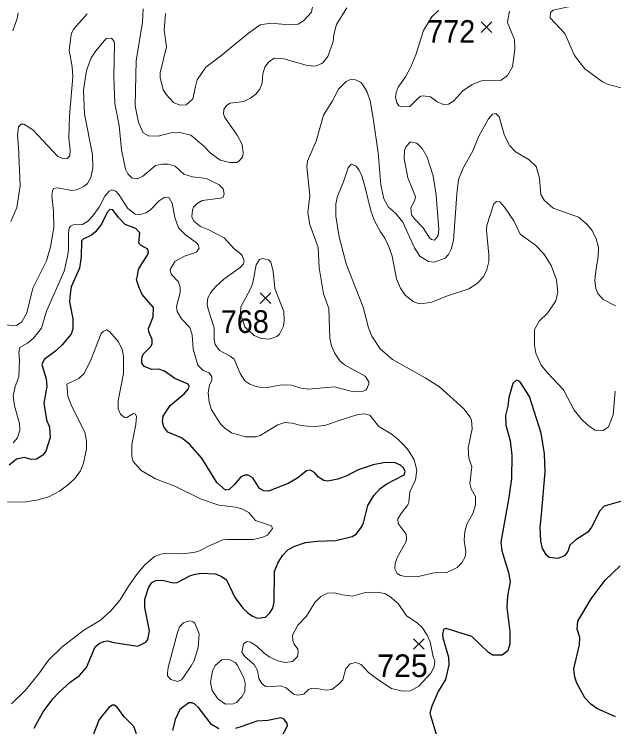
# Model space of a CAD drawing. Extents: x 294.2 to 320.3, y 7482.7 to 7510.7.
# Drawn here: x 306.916 to 309.032, y 7498.807 to 7501.322 of the extents above; entities that cross this region are included whole.
import ezdxf
from ezdxf.enums import TextEntityAlignment as Align

# ---------------------------------------------------------------- set-up
doc = ezdxf.new("R2010")
doc.units = 0
doc.header["$LTSCALE"] = 0.032
for name, color, linetype, lineweight in [('1', 7, 'Continuous', 25), ('2', 7, 'Continuous', 13), ('21', 7, 'Continuous', 25)]:
    doc.layers.add(name, color=color, linetype=linetype, lineweight=lineweight)
doc.layers.add('61', color=7, linetype='Continuous')

msp = doc.modelspace()

# ---------------------------------------------------------------- linework, layer by layer
at = {"layer": '1'}
for points in [[(307.5349, 7499.8047), (307.5058, 7499.8267), (307.4579, 7499.8471), (307.4445, 7499.8652), (307.4394, 7499.8833), (307.4418, 7499.9029), (307.452, 7499.9202), (307.4661, 7499.9407), (307.5157, 7499.9816), (307.5298, 7499.9981), (307.5338, 7500.0075), (307.5298, 7500.0162), (307.4833, 7500.0366), (307.4463, 7500.0625), (307.4266, 7500.0696), (307.4015, 7500.068), (307.3748, 7500.079), (307.3669, 7500.0908), (307.3669, 7500.1074), (307.3708, 7500.1223), (307.3968, 7500.1475), (307.4031, 7500.1585), (307.4033, 7500.1734), (307.3912, 7500.2007), (307.3904, 7500.2132), (307.4062, 7500.2541), (307.407, 7500.2864), (307.3671, 7500.3328), (307.3561, 7500.3595), (307.3479, 7500.3844), (307.3508, 7500.3988), (307.3541, 7500.421), (307.3665, 7500.4404), (307.3858, 7500.4719), (307.3897, 7500.4821), (307.3881, 7500.4931), (307.3639, 7500.5062), (307.3559, 7500.5144), (307.359, 7500.5505), (307.3457, 7500.5655), (307.3071, 7500.5796), (307.2838, 7500.604), (307.2642, 7500.6315), (307.2531, 7500.6323), (307.2453, 7500.6244), (307.2243, 7500.5812), (307.2033, 7500.5537), (307.1892, 7500.5422), (307.1592, 7500.5282), (307.1535, 7500.5224), (307.1522, 7500.4662), (307.1458, 7500.4254), (307.1164, 7500.3602), (307.1133, 7500.3347), (307.1115, 7500.3064), (307.1225, 7500.2474), (307.1225, 7500.2113), (307.117, 7500.1932), (307.0852, 7500.1555), (307.0624, 7500.1334), (307.0215, 7500.1028), (307.0136, 7500.0855), (307.029, 7500.0351), (307.0313, 7500.0076), (307.0203, 7499.9494), (307.0301, 7499.8905), (307.0403, 7499.8645), (307.043, 7499.8284), (307.0277, 7499.7793), (307.0168, 7499.7658), (306.9951, 7499.7518), (306.9753, 7499.7505), (306.9524, 7499.7569), (306.9243, 7499.7518), (306.8987, 7499.7301)], [(309.0967, 7499.6135), (308.998, 7499.5852), (308.9823, 7499.5695), (308.9532, 7499.5113), (308.9399, 7499.494), (308.8978, 7499.4673), (308.8774, 7499.4484), (308.8695, 7499.4256), (308.8585, 7499.4107), (308.8349, 7499.4013), (308.8042, 7499.4044), (308.794, 7499.4123), (308.7799, 7499.4367), (308.7746, 7499.4626), (308.7726, 7499.5098), (308.7771, 7499.5558), (308.7899, 7499.7072), (308.788, 7499.7705), (308.7761, 7499.8429), (308.7345, 7499.9726), (308.6999, 7500.0261), (308.6889, 7500.0308), (308.6755, 7500.019), (308.6618, 7499.9697), (308.6581, 7499.939), (308.6494, 7499.906), (308.651, 7499.8714), (308.6666, 7499.8156), (308.6724, 7499.7639), (308.6705, 7499.6835), (308.6613, 7499.6159), (308.6328, 7499.4587), (308.6367, 7499.4281), (308.6609, 7499.3515), (308.666, 7499.3183), (308.6571, 7499.2685), (308.6545, 7499.2276), (308.6647, 7499.1428), (308.6655, 7499.0995), (308.6576, 7499.0744), (308.6379, 7499.0594), (308.6041, 7499.0594), (308.59, 7499.0689), (308.5307, 7499.125), (308.4403, 7499.1541), (308.4309, 7499.1501), (308.427, 7499.1336), (308.4285, 7499.1203), (308.4485, 7499.0528), (308.4493, 7499.0252), (308.4379, 7498.9733), (308.412, 7498.9309), (308.39, 7498.8798), (308.3833, 7498.8546), (308.4077, 7498.7721)], [(307.7152, 7499.6896), (307.6932, 7499.6621), (307.6743, 7499.6448), (307.6617, 7499.6417), (307.6313, 7499.6692), (307.5781, 7499.755), (307.5349, 7499.8047)], [(306.9862, 7498.8018), (307.0176, 7498.8592), (307.0526, 7498.9056), (307.073, 7498.9276), (307.1131, 7498.9646), (307.1448, 7498.9866), (307.1705, 7499.0162), (307.2019, 7499.0886), (307.2161, 7499.1004), (307.2318, 7499.1082), (307.2452, 7499.1106), (307.2676, 7499.1043), (307.3525, 7499.0918), (307.38, 7499.1051), (307.3871, 7499.1153), (307.3934, 7499.146), (307.3771, 7499.2278), (307.3771, 7499.2577), (307.3893, 7499.297), (307.4011, 7499.3159), (307.4153, 7499.3237), (307.4389, 7499.3245), (307.4774, 7499.3151), (307.4916, 7499.3159), (307.5385, 7499.3404), (307.5558, 7499.3459), (307.5766, 7499.349), (307.6246, 7499.3467), (307.6458, 7499.338), (307.6647, 7499.3255), (307.6949, 7499.2635), (307.7244, 7499.2242), (307.7409, 7499.2093), (307.7574, 7499.1975), (307.7747, 7499.1904), (307.8022, 7499.1936), (307.818, 7499.2085), (307.8282, 7499.2258), (307.8337, 7499.2463), (307.8349, 7499.3547), (307.8459, 7499.3846), (307.8624, 7499.4113), (307.8821, 7499.431), (307.9029, 7499.4428), (307.9445, 7499.4577), (307.9846, 7499.4624), (308.0511, 7499.4648), (308.1092, 7499.4789), (308.1226, 7499.4868), (308.1415, 7499.512), (308.1488, 7499.5269), (308.1641, 7499.5881), (308.185, 7499.6234), (308.2062, 7499.6462), (308.229, 7499.6635), (308.2919, 7499.6958), (308.2958, 7499.7076), (308.2903, 7499.7209), (308.2793, 7499.7304), (308.2577, 7499.7398), (308.2191, 7499.7383), (308.1822, 7499.732), (308.1299, 7499.7139), (308.0898, 7499.6927), (308.0575, 7499.6809), (308.0229, 7499.6738), (308.0084, 7499.6762), (307.9903, 7499.688), (307.9762, 7499.7045), (307.9604, 7499.7132), (307.9479, 7499.7108), (307.9172, 7499.6857), (307.883, 7499.666), (307.8138, 7499.6385), (307.7973, 7499.6401), (307.7816, 7499.648), (307.7576, 7499.6857), (307.7419, 7499.6951), (307.7293, 7499.6951), (307.7152, 7499.6896)], [(309.0381, 7498.8419), (308.9725, 7498.8711), (308.9504, 7498.8868), (308.93, 7498.9096), (308.9013, 7498.9607), (308.8942, 7498.9819), (308.8911, 7499.011), (308.9111, 7499.0959), (308.9119, 7499.1219), (308.9032, 7499.151), (308.9056, 7499.1793), (308.9522, 7499.2579), (309.001, 7499.324), (309.0547, 7499.3751)], [(307.6377, 7498.7996), (307.6125, 7498.8146), (307.5666, 7498.8745), (307.5538, 7498.8866), (307.5436, 7498.8918), (307.5321, 7498.8918), (307.5002, 7498.8675), (307.4834, 7498.8325), (307.4747, 7498.7932)], [(307.3378, 7498.8081), (307.304, 7498.8419), (307.2788, 7498.8757), (307.2702, 7498.8836), (307.2631, 7498.8828), (307.2498, 7498.875), (307.2154, 7498.8325)], [(307.2154, 7498.8325), (307.1714, 7498.7184)], [(307.8579, 7498.7682), (307.8799, 7498.8098), (307.8791, 7498.8185), (307.8681, 7498.8334), (307.8571, 7498.8381), (307.8111, 7498.8295), (307.7726, 7498.8264), (307.7195, 7498.8083), (307.6967, 7498.8012)], [(307.3472, 7498.7822), (307.3378, 7498.8081)]]:
    msp.add_lwpolyline(points, dxfattribs=at)
at = {"layer": '2'}
for points in [[(307.9675, 7501.74), (308.0026, 7501.7151), (308.0141, 7501.6985), (308.0314, 7501.6628), (308.0435, 7501.6181), (308.0454, 7501.5951), (308.0339, 7501.53), (308.0211, 7501.4968), (308.0001, 7501.461), (307.9815, 7501.4201), (307.9656, 7501.3288), (307.9369, 7501.2982), (307.9177, 7501.2873), (307.873, 7501.2854), (307.822, 7501.2899), (307.7837, 7501.2841), (307.7428, 7501.2548), (307.6445, 7501.1737), (307.5927, 7501.1347), (307.5621, 7501.0907), (307.5556, 7501.067)], [(309.0344, 7501.3626), (309.0108, 7501.3761), (308.954, 7501.392), (308.9368, 7501.3914), (308.9125, 7501.3844), (308.8831, 7501.355), (308.8722, 7501.3486), (308.8333, 7501.3397), (308.818, 7501.3358), (308.8084, 7501.3282), (308.8077, 7501.3096), (308.8588, 7501.2541), (308.8933, 7501.1762), (308.9297, 7501.1296), (308.9923, 7501.0837), (309.0095, 7501.0753), (309.0964, 7501.0517)], [(308.0901, 7501.3448), (308.0531, 7501.2861), (308.0435, 7501.2503), (308.0416, 7501.226), (308.0231, 7501.1724), (308.0039, 7501.1488), (307.9816, 7501.1398), (307.9727, 7501.1392), (307.9458, 7501.1424), (307.8679, 7501.1641), (307.8334, 7501.1667), (307.813, 7501.1532), (307.8002, 7501.1347), (307.7938, 7501.1111), (307.7913, 7501.0792), (307.783, 7501.0575), (307.769, 7501.0402), (307.7498, 7501.0262), (307.7262, 7501.014), (307.6777, 7501.0083), (307.6649, 7501), (307.6553, 7500.9853), (307.654, 7500.9707), (307.6592, 7500.9579), (307.7026, 7500.8953), (307.7204, 7500.8627), (307.7243, 7500.8315), (307.7217, 7500.8174), (307.7102, 7500.804), (307.7013, 7500.7989), (307.6777, 7500.7982), (307.6432, 7500.8072), (307.6074, 7500.8327), (307.5844, 7500.857), (307.5397, 7500.8953), (307.5002, 7500.9049), (307.4683, 7500.9036), (307.4236, 7500.8921), (307.3904, 7500.8927), (307.3705, 7500.9036), (307.354, 7500.94), (307.3431, 7500.9987), (307.3469, 7501.1571), (307.3686, 7501.2937), (307.3712, 7501.341)], [(308.4138, 7501.3346), (308.3896, 7501.3128), (308.3608, 7501.265), (308.3334, 7501.1788), (308.3155, 7501.1367), (308.2964, 7501.1009), (308.2714, 7501.0651), (308.2637, 7501.046), (308.2612, 7501.0281), (308.2663, 7501.0102), (308.2733, 7500.9981), (308.2823, 7500.9949), (308.3117, 7500.9962), (308.341, 7501.0255), (308.3513, 7501.0332), (308.3596, 7501.0345), (308.3851, 7501.03), (308.4087, 7501.0127), (308.4311, 7501.0032), (308.4489, 7501.0051), (308.4674, 7501.016), (308.4994, 7501.0517), (308.5319, 7501.0734), (308.5651, 7501.0868), (308.6347, 7501.0888), (308.6571, 7501.1054), (308.6749, 7501.1367), (308.6826, 7501.1992), (308.682, 7501.2331), (308.6571, 7501.2924), (308.6577, 7501.3027), (308.6641, 7501.3333)], [(307.1739, 7501.3231), (307.1267, 7501.2707), (307.1183, 7501.2554), (307.1152, 7501.2414), (307.1094, 7501.1954), (307.1209, 7501.1367), (307.1234, 7501.1009), (307.1107, 7500.963), (307.1088, 7500.8851), (307.1139, 7500.843), (307.112, 7500.8225), (307.103, 7500.8129), (307.0916, 7500.8117), (307.0698, 7500.8199), (306.9811, 7500.9145), (306.9498, 7500.9343), (306.9402, 7500.9336), (306.9306, 7500.924), (306.9281, 7500.894), (306.9313, 7500.8532), (306.9364, 7500.7165), (306.9255, 7500.6399), (306.9045, 7500.5901)], [(306.93, 7501.3269), (306.9262, 7501.3065), (306.9115, 7501.2637)], [(307.5556, 7501.067), (307.5468, 7501.0236), (307.5232, 7501.0025), (307.5002, 7501.0007), (307.4778, 7501.0102), (307.4529, 7501.037), (307.4421, 7501.0549), (307.4306, 7501.0984), (307.4306, 7501.115), (307.4536, 7501.2069), (307.4452, 7501.2656), (307.4497, 7501.3244)], [(307.9815, 7500.8736), (307.9509, 7500.8034), (307.9483, 7500.7829), (307.9592, 7500.6821), (307.9522, 7500.6208), (307.9598, 7500.5799), (307.9892, 7500.4982), (307.9924, 7500.4267), (308.0071, 7500.3347), (308.0262, 7500.2837), (308.0301, 7500.1789), (308.0352, 7500.1521), (308.046, 7500.1272), (308.0646, 7500.0985), (308.0818, 7500.0844), (308.1546, 7500.0448), (308.1674, 7500.0244), (308.1674, 7500.0168), (308.1603, 7500.0001), (308.1565, 7499.995), (308.1444, 7499.9899), (308.1131, 7499.9886), (308.0467, 7500.0065), (307.9548, 7499.9982), (307.9292, 7500.0021), (307.8935, 7500.0129), (307.859, 7500.0142), (307.8104, 7500.004), (307.7926, 7500.0034), (307.7658, 7500.0097), (307.7479, 7500.0161), (307.7294, 7500.0282), (307.7128, 7500.0538), (307.6917, 7500.1042), (307.6777, 7500.1151), (307.64, 7500.1349), (307.6253, 7500.1559), (307.6221, 7500.1738), (307.6221, 7500.2147), (307.6004, 7500.2811), (307.5972, 7500.299), (307.5991, 7500.3213), (307.6093, 7500.3398), (307.6259, 7500.3602), (307.6553, 7500.3864), (307.7134, 7500.4279), (307.7249, 7500.4407), (307.7274, 7500.4509), (307.7204, 7500.4701), (307.7115, 7500.4803), (307.6917, 7500.4944), (307.6572, 7500.5333), (307.6023, 7500.5614), (307.573, 7500.5722), (307.5499, 7500.592), (307.5429, 7500.6067), (307.5448, 7500.631), (307.5487, 7500.6406), (307.5615, 7500.6539), (307.5793, 7500.6641), (307.6444, 7500.6725), (307.6528, 7500.6763), (307.6572, 7500.6884), (307.6528, 7500.7056), (307.6387, 7500.7197), (307.594, 7500.7427), (307.5449, 7500.7478), (307.5148, 7500.7574), (307.4842, 7500.7861), (307.4593, 7500.7925), (307.4389, 7500.7931), (307.4146, 7500.788), (307.3686, 7500.7497), (307.3501, 7500.7414), (307.3322, 7500.7433), (307.3175, 7500.7587), (307.3086, 7500.7753), (307.2945, 7500.843), (307.2869, 7500.9298), (307.2716, 7501.0064), (307.2677, 7501.1009), (307.2703, 7501.2171), (307.269, 7501.226), (307.2594, 7501.2381), (307.2409, 7501.2369), (307.2039, 7501.1928), (307.188, 7501.1686), (307.1707, 7501.1239), (307.1605, 7501.0537), (307.1643, 7500.9694), (307.1924, 7500.8264), (307.1931, 7500.7791), (307.1892, 7500.7561), (307.1867, 7500.7452), (307.1745, 7500.7242)], [(308.1208, 7501.09), (308.1022, 7501.0913), (308.0875, 7501.0843), (308.0607, 7501.0575), (308.0397, 7501.0166), (308.0071, 7500.9655), (307.9815, 7500.8736)], [(309.0376, 7500.2932), (308.9948, 7500.3156), (308.9757, 7500.336), (308.9686, 7500.3539), (308.9648, 7500.3833), (308.9699, 7500.4241), (308.977, 7500.4656), (308.9776, 7500.4982), (308.9699, 7500.5288), (308.9553, 7500.5582), (308.9367, 7500.5805), (308.9074, 7500.6061), (308.818, 7500.638), (308.786, 7500.6655), (308.7739, 7500.6859), (308.7694, 7500.7434), (308.7579, 7500.7842), (308.7337, 7500.8078), (308.6845, 7500.8365), (308.6647, 7500.857), (308.6462, 7500.894), (308.6271, 7500.9598), (308.6162, 7500.9719), (308.6034, 7500.9687), (308.59, 7500.9528), (308.5562, 7500.8915), (308.5345, 7500.8404), (308.5, 7500.7791), (308.4841, 7500.7383), (308.4777, 7500.6872), (308.4668, 7500.5237), (308.4585, 7500.4931), (308.4489, 7500.4739), (308.4368, 7500.4605), (308.3979, 7500.4471), (308.3781, 7500.449), (308.3474, 7500.4682), (308.3283, 7500.4969), (308.2874, 7500.5876), (308.2618, 7500.6194), (308.2369, 7500.6405), (308.2203, 7500.6706), (308.2095, 7500.7204), (308.1999, 7500.8327), (308.1833, 7500.9553), (308.1725, 7501.0166), (308.161, 7501.0473), (308.1488, 7501.069), (308.1399, 7501.0805), (308.1208, 7501.09)], [(308.6085, 7500.6533), (308.5843, 7500.5761), (308.5824, 7500.5582), (308.5913, 7500.4726), (308.5906, 7500.4497), (308.5824, 7500.4165), (308.5709, 7500.3935), (308.5492, 7500.3717), (308.5205, 7500.3526), (308.449, 7500.329), (308.3864, 7500.3047), (308.3449, 7500.2996), (308.3238, 7500.3079), (308.2957, 7500.3309), (308.2791, 7500.3552), (308.265, 7500.3884), (308.2497, 7500.4675), (308.2395, 7500.4982), (308.2242, 7500.5314), (308.2082, 7500.5537), (308.1859, 7500.5952), (308.1744, 7500.6284), (308.1539, 7500.7153), (308.1431, 7500.751), (308.1335, 7500.7715), (308.122, 7500.7874), (308.1048, 7500.7925), (308.0946, 7500.7803), (308.078, 7500.7306), (308.0569, 7500.6795), (308.0505, 7500.6527), (308.0505, 7500.6093), (308.0633, 7500.5365), (308.0875, 7500.4407), (308.1475, 7500.2875), (308.1661, 7500.2153), (308.1776, 7500.1859), (308.2076, 7500.1412), (308.2504, 7500.1036), (308.366, 7500.0384), (308.417, 7500.0072), (308.5032, 7499.9293), (308.5255, 7499.8993), (308.5294, 7499.8891), (308.5319, 7499.8584), (308.5179, 7499.792), (308.5204, 7499.755), (308.5306, 7499.7243), (308.5236, 7499.6656), (308.5288, 7499.6465), (308.5434, 7499.6196), (308.5441, 7499.5903), (308.5351, 7499.5622), (308.5134, 7499.5226), (308.5064, 7499.4958), (308.5038, 7499.4651), (308.5096, 7499.4243), (308.5076, 7499.4064), (308.4962, 7499.386), (308.4789, 7499.3687), (308.44, 7499.3502), (308.403, 7499.3514), (308.3366, 7499.3361), (308.297, 7499.3368), (308.2791, 7499.3406), (308.2676, 7499.3483), (308.2593, 7499.3642), (308.2606, 7499.3834), (308.2676, 7499.4038), (308.2989, 7499.4613), (308.3008, 7499.4715), (308.2989, 7499.4862), (308.2708, 7499.5245), (308.2695, 7499.5404), (308.281, 7499.5602), (308.3053, 7499.5903), (308.3091, 7499.5992), (308.3123, 7499.6362), (308.3327, 7499.6784), (308.3365, 7499.7129), (308.327, 7499.7486), (308.3078, 7499.7818), (308.2925, 7499.7997), (308.2701, 7499.822), (308.2459, 7499.8405), (308.2025, 7499.8667), (308.1712, 7499.9063), (308.1527, 7499.912), (308.1284, 7499.9089), (308.0595, 7499.8865), (308.0161, 7499.8718), (307.9739, 7499.8654), (307.9292, 7499.8699), (307.8973, 7499.8788), (307.8705, 7499.8814)], [(307.6591, 7499.8609), (307.6438, 7499.8757), (307.6125, 7499.9261), (307.6036, 7499.9529), (307.6004, 7499.9861), (307.6055, 7500.0129), (307.6132, 7500.0301), (307.6132, 7500.0423), (307.6042, 7500.0563), (307.5832, 7500.0647), (307.5634, 7500.0832), (307.5474, 7500.1394), (307.5442, 7500.1904), (307.5353, 7500.216), (307.5059, 7500.2472), (307.4912, 7500.2722), (307.4886, 7500.29), (307.5014, 7500.3398), (307.5014, 7500.3577), (307.4957, 7500.3769), (307.4702, 7500.4043), (307.4669, 7500.4215), (307.4829, 7500.449), (307.5168, 7500.4675), (307.5595, 7500.4822), (307.5685, 7500.4963), (307.5653, 7500.5077), (307.5576, 7500.516), (307.5206, 7500.5435), (307.4963, 7500.5684), (307.4823, 7500.6042), (307.4733, 7500.6552), (307.4631, 7500.6737), (307.458, 7500.6768), (307.4453, 7500.6751), (307.427, 7500.6634), (307.3971, 7500.6317), (307.381, 7500.6206), (307.3586, 7500.6144), (307.3425, 7500.6158), (307.3173, 7500.6358), (307.2857, 7500.6854), (307.2748, 7500.6976), (307.2604, 7500.7021), (307.2507, 7500.6976), (307.2363, 7500.6801), (307.216, 7500.6412), (307.1937, 7500.6106), (307.1752, 7500.5914), (307.1567, 7500.5793), (307.1246, 7500.5781), (307.1143, 7500.5737), (307.1097, 7500.567), (307.1074, 7500.5497), (307.1075, 7500.4905), (307.1043, 7500.4669), (307.0928, 7500.4152), (307.0296, 7500.2734), (307.0124, 7500.2134), (306.9843, 7500.1789), (306.9626, 7500.161), (306.9357, 7500.1451), (306.9319, 7500.1279), (306.9344, 7500.1011), (306.9326, 7500.0416), (306.9198, 7500.0078), (306.9127, 7499.9734), (306.9166, 7499.9402), (306.9351, 7499.8776), (306.9357, 7499.8533), (306.9275, 7499.8265), (306.9128, 7499.8093)], [(307.1745, 7500.7242), (307.1618, 7500.714), (307.1375, 7500.7018), (307.1196, 7500.6993), (307.0686, 7500.7095), (307.0551, 7500.7069), (307.0506, 7500.6986)], [(307.0506, 7500.6986), (307.0488, 7500.6795), (307.0545, 7500.6272), (307.0552, 7500.5697), (307.0437, 7500.5007), (307.0302, 7500.4515), (306.9811, 7500.3552), (306.9607, 7500.2683), (306.9427, 7500.2364), (306.9242, 7500.2236), (306.8694, 7500.2255)], [(308.7554, 7500.5065), (308.7018, 7500.5454), (308.6794, 7500.5927), (308.6462, 7500.6412), (308.6296, 7500.6597), (308.6175, 7500.661), (308.6085, 7500.6533)], [(309.0363, 7499.9912), (309.0299, 7499.9082), (309.0134, 7499.8654), (308.9942, 7499.8527), (308.9654, 7499.8539), (308.9387, 7499.8724), (308.9182, 7499.8922), (308.8927, 7499.9248), (308.855, 7499.9963), (308.7975, 7500.0557), (308.7758, 7500.0832), (308.7573, 7500.1253), (308.7516, 7500.1536), (308.7522, 7500.2088), (308.7701, 7500.2396), (308.7982, 7500.2664), (308.8269, 7500.3105), (308.8345, 7500.3411), (308.8301, 7500.3845), (308.811, 7500.4356), (308.7854, 7500.4758), (308.7554, 7500.5065)], [(306.8923, 7499.5992), (306.9568, 7499.6011), (306.9945, 7499.6068), (307.0379, 7499.619), (307.0762, 7499.6381), (307.1088, 7499.663), (307.1305, 7499.6841), (307.1496, 7499.7103), (307.1599, 7499.7371), (307.1714, 7499.7882), (307.1714, 7499.815), (307.165, 7499.8469), (307.119, 7499.9376), (307.105, 7499.9734), (307.1011, 7500.0161), (307.1439, 7500.0366), (307.1624, 7500.0544), (307.188, 7500.1049), (307.223, 7500.1949), (307.2294, 7500.2026), (307.2422, 7500.2077), (307.2537, 7500.2013), (307.2837, 7500.1655), (307.2965, 7500.1381), (307.3016, 7500.1151), (307.3022, 7500.0538), (307.2824, 7499.9568), (307.2824, 7499.9286), (307.2907, 7499.9108)], [(307.2907, 7499.9108), (307.3048, 7499.898), (307.3105, 7499.8974), (307.3367, 7499.9127), (307.3424, 7499.9114), (307.3476, 7499.9031), (307.3456, 7499.8738)], [(307.3456, 7499.8738), (307.3316, 7499.8035), (307.331, 7499.7614), (307.3361, 7499.7435), (307.3635, 7499.7115), (307.4146, 7499.6816), (307.4823, 7499.656), (307.5755, 7499.6107), (307.6381, 7499.5896), (307.6968, 7499.5826), (307.7198, 7499.5756), (307.7441, 7499.5634), (307.7677, 7499.5353), (307.8245, 7499.5156), (307.8277, 7499.5072), (307.8104, 7499.483), (307.7939, 7499.476), (307.7607, 7499.4683), (307.6662, 7499.4676), (307.6527, 7499.4664), (307.6394, 7499.4607), (307.6062, 7499.4472), (307.5704, 7499.4274), (307.5551, 7499.4229), (307.5117, 7499.4178), (307.4517, 7499.4191), (307.4338, 7499.4166), (307.4114, 7499.4076), (307.3769, 7499.3789), (307.3514, 7499.3476), (307.3188, 7499.3036), (307.2901, 7499.2544), (307.2575, 7499.2167), (307.2205, 7499.1835), (307.1611, 7499.1478), (307.0839, 7499.0884), (307.0373, 7499.0418), (307.0015, 7498.9927), (306.9555, 7498.9364), (306.9064, 7498.8873)], [(307.8705, 7499.8814), (307.8462, 7499.8731), (307.7837, 7499.8348), (307.7683, 7499.8303), (307.7326, 7499.8303), (307.6828, 7499.845), (307.6591, 7499.8609)]]:
    msp.add_lwpolyline(points, dxfattribs=at)
for points in [[(308.3167, 7500.7158), (308.3321, 7500.677), (308.3302, 7500.6667), (308.3155, 7500.638), (308.3181, 7500.6144), (308.3283, 7500.5997), (308.3595, 7500.5678), (308.3819, 7500.5326), (308.3889, 7500.5269), (308.3992, 7500.525), (308.4125, 7500.541), (308.4144, 7500.562), (308.4055, 7500.6833), (308.394, 7500.751), (308.373, 7500.8174), (308.3557, 7500.8481), (308.3372, 7500.8672), (308.3142, 7500.8717), (308.2982, 7500.8544), (308.2931, 7500.8404), (308.2918, 7500.8123), (308.3053, 7500.7446)], [(307.8519, 7500.1923), (307.843, 7500.184), (307.8156, 7500.1751), (307.7875, 7500.1776), (307.7632, 7500.1878), (307.7294, 7500.2182), (307.7145, 7500.263), (307.7158, 7500.2897), (307.7498, 7500.3526), (307.7575, 7500.3743), (307.7702, 7500.4369), (307.7817, 7500.456), (307.7926, 7500.4592), (307.813, 7500.4547), (307.8213, 7500.4465), (307.8303, 7500.4152), (307.836, 7500.3539), (307.8679, 7500.2722), (307.8692, 7500.2415), (307.866, 7500.2211)], [(308.0748, 7499.2729), (308.0454, 7499.2799), (308.0212, 7499.2786), (307.9982, 7499.2672), (307.9764, 7499.2455), (307.9477, 7499.197), (307.9164, 7499.165), (307.8985, 7499.1306), (307.8992, 7499.1114), (307.9043, 7499.0986), (307.9171, 7499.0808), (307.9177, 7499.0705), (307.9152, 7499.0552), (307.8979, 7499.0373), (307.873, 7499.0335), (307.8462, 7499.0399), (307.8181, 7499.0526), (307.7983, 7499.0667), (307.7721, 7499.0916), (307.7504, 7499.1057), (307.7364, 7499.1075), (307.7249, 7499.0992), (307.7198, 7499.0686), (307.7306, 7499.0533), (307.7632, 7499.0265), (307.7741, 7499.0054), (307.7798, 7498.9773), (307.79, 7498.9595), (307.8022, 7498.9486), (307.813, 7498.9473), (307.8558, 7498.9517), (307.8756, 7498.9441), (307.9011, 7498.9218), (307.9165, 7498.9185), (307.9381, 7498.9224), (307.9547, 7498.939), (307.9637, 7498.9415), (307.9905, 7498.9409), (308.0173, 7498.9358), (308.0365, 7498.939), (308.062, 7498.9569), (308.0754, 7498.9728), (308.0863, 7499.0131), (308.101, 7499.029), (308.1221, 7499.0335), (308.1406, 7499.0265), (308.1661, 7498.9984), (308.1987, 7498.9735), (308.2478, 7498.9422), (308.2817, 7498.9333), (308.3123, 7498.9326), (308.3442, 7498.9505), (308.3864, 7498.9958), (308.3985, 7499.0188), (308.3998, 7499.0392), (308.394, 7499.0539), (308.3838, 7499.1063), (308.373, 7499.1306), (308.3551, 7499.1574), (308.3385, 7499.174), (308.3008, 7499.1989), (308.2708, 7499.2423), (308.2414, 7499.2665), (308.2235, 7499.2768), (308.1961, 7499.2825), (308.1514, 7499.2799), (308.1093, 7499.2684)], [(307.4918, 7499.1401), (307.4587, 7499.0156), (307.4567, 7498.9978), (307.4574, 7498.9862), (307.4682, 7498.9735), (307.4925, 7498.9665), (307.5059, 7498.9728), (307.5155, 7498.985), (307.541, 7499.022), (307.5506, 7499.0412), (307.5653, 7499.0872), (307.5691, 7499.1344), (307.5532, 7499.1727), (307.5474, 7499.1778), (307.5359, 7499.181), (307.5135, 7499.174), (307.4989, 7499.1599)], [(307.7025, 7499.0251), (307.6955, 7499.0335), (307.6751, 7499.0443), (307.6483, 7499.0437), (307.6253, 7499.0227), (307.6157, 7499.0029), (307.6087, 7498.9633), (307.6151, 7498.9352), (307.6349, 7498.9051), (307.6617, 7498.8866), (307.6892, 7498.8879), (307.7006, 7498.8924), (307.7198, 7498.9128), (307.7294, 7498.9314), (307.7313, 7498.9607), (307.7262, 7498.9799)]]:
    msp.add_lwpolyline(points, close=True, dxfattribs=at)
at = {"layer": '21'}
for p, q in [((308.5636, 7501.2951), (308.6011, 7501.2576)), ((308.6011, 7501.2951), (308.5636, 7501.2576)), ((307.7838, 7500.3385), (307.8213, 7500.301)), ((307.8213, 7500.3385), (307.7838, 7500.301)), ((308.3247, 7499.1178), (308.3622, 7499.0803)), ((308.3622, 7499.1178), (308.3247, 7499.0803))]:
    msp.add_line(p, q, dxfattribs=at)

# ---------------------------------------------------------------- texts
at = {"layer": '61', "width": 0.95}
for s, p in [('772', (308.4583, 7501.2211)), ('768', (307.7297, 7500.1971))]:
    msp.add_text(s, height=0.08, dxfattribs=at).set_placement(p, align=Align.CENTER)
at = {"layer": '61'}
msp.add_text('725', height=0.08, dxfattribs=at).set_placement((308.2862, 7498.9823), align=Align.CENTER)

doc.saveas('drawing.dxf')
